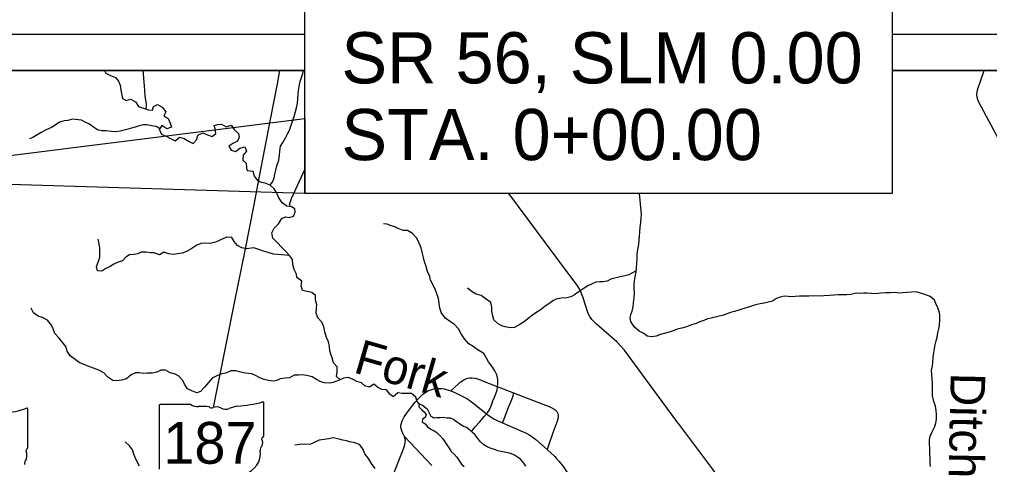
# Model space of a CAD drawing. Extents: x 0 to 36.5, y 0 to 25.3.
# Drawn here: x 3.798 to 6.451, y 19.822 to 21.04 of the extents above; entities that cross this region are included whole.
import ezdxf

# ---------------------------------------------------------------- set-up
doc = ezdxf.new("R2010")
doc.units = 0
for name, color, linetype in [('DV_X_Township_Line', 7, 'Continuous'), ('GM_X_County_Road', 7, 'Continuous'), ('GM_X_Major_Lake', 7, 'Continuous'), ('GM_X_Minor_River', 7, 'Continuous'), ('GM_X_Minor_River_Text', 7, 'Continuous'), ('GM_X_State_Route', 7, 'Continuous'), ('GM_X_State_Shield', 7, 'Continuous'), ('GM_X_Township_Road', 7, 'Continuous'), ('SH_Cut_Line', 7, 'Continuous'), ('SH_Data', 7, 'Continuous'), ('SH_Text', 7, 'Continuous'), ('SN_X_Public', 7, 'Continuous')]:
    doc.layers.add(name, color=color, linetype=linetype)

msp = doc.modelspace()

# ---------------------------------------------------------------- linework, layer by layer
at = {"layer": 'DV_X_Township_Line'}
for points in [[(4.5783, 20.9), (3.3366, 20.9), (3.2612, 20.6041), (2.8463, 19.037), (2.6265, 18.2595), (2.5271, 17.8912), (2.5226, 17.8751), (2.5165, 17.8524), (2.5144, 17.8445), (2.4192, 17.4891), (2.3437, 17.2326), (2.3403, 17.2198), (2.1039, 16.2931), (2.4938, 16.3413), (4.0938, 16.595), (4.8891, 16.7511), (5.1383, 16.6527), (6.6079, 15.9978)], [(6.9868, 20.9), (6.1845, 20.9)]]:
    msp.add_lwpolyline(points, dxfattribs=at)
at = {"layer": 'GM_X_County_Road'}
for points in [[(6.5695, 20.538), (6.4286, 20.8002), (6.4203, 20.8169), (6.4171, 20.8261), (6.416, 20.8349), (6.418, 20.8471), (6.4364, 20.9)], [(5.6026, 19.9308), (5.5959, 19.9396), (5.4521, 20.1349), (5.432, 20.1577), (5.3759, 20.2062), (5.3629, 20.2192), (5.3574, 20.2272), (5.3532, 20.2358), (5.339, 20.281), (5.331, 20.2995), (5.3245, 20.3101), (5.2656, 20.3899), (5.1365, 20.5634)], [(6.27, 19.0102), (6.154, 19.0787), (5.9106, 19.2156), (5.8953, 19.2261), (5.8889, 19.2321), (5.8831, 19.2395), (5.874, 19.2561), (5.8715, 19.2656), (5.8706, 19.2751), (5.8855, 19.4287), (5.8883, 19.4658), (5.8884, 19.4882), (5.8862, 19.5068), (5.882, 19.5251), (5.8767, 19.5387), (5.871, 19.5497), (5.8458, 19.5924), (5.8291, 19.6185), (5.7328, 19.7554), (5.6929, 19.8107), (5.6026, 19.9308)]]:
    msp.add_lwpolyline(points, dxfattribs=at)
at = {"layer": 'GM_X_Major_Lake'}
msp.add_lwpolyline([(5.1824, 19.8174), (5.1771, 19.8257), (5.1691, 19.836), (5.1596, 19.8425), (5.1517, 19.8478), (5.1437, 19.8516), (5.138, 19.8536), (5.1293, 19.8551), (5.1202, 19.857), (5.1145, 19.8578), (5.1061, 19.8601), (5.0966, 19.8632), (5.0883, 19.8662), (5.0769, 19.8708), (5.0678, 19.8762), (5.0587, 19.8845), (5.0515, 19.8933), (5.0443, 19.9032), (5.0368, 19.9101), (5.0288, 19.9169), (5.0205, 19.9234), (5.0106, 19.9268), (5.0011, 19.9337), (4.9932, 19.939), (4.9844, 19.9455), (4.9765, 19.9486), (4.967, 19.9494), (4.9567, 19.9505), (4.948, 19.9502), (4.9396, 19.9502), (4.9317, 19.9487), (4.9233, 19.9533), (4.9195, 19.9624), (4.915, 19.9715), (4.9078, 19.9773), (4.9002, 19.9834), (4.8907, 19.9883), (4.8903, 19.98), (4.8979, 19.9723), (4.9059, 19.9659), (4.91, 19.9583), (4.9077, 19.9507), (4.8997, 19.9465), (4.899, 19.9389), (4.9069, 19.934), (4.9137, 19.9256), (4.9228, 19.9191), (4.9316, 19.9145), (4.9395, 19.9099), (4.9471, 19.9012), (4.9554, 19.8924), (4.9615, 19.884), (4.9664, 19.8761), (4.9728, 19.8669), (4.9785, 19.8582), (4.9868, 19.8509), (4.994, 19.8425), (5.0012, 19.8315), (5.0065, 19.8235), (5.0137, 19.8167)], dxfattribs=at)
at = {"layer": 'GM_X_Minor_River'}
for points in [[(4.0305, 20.9), (4.0339, 20.893), (4.0467, 20.8865), (4.06, 20.8807), (4.0682, 20.8707), (4.0731, 20.8601), (4.0748, 20.8475), (4.0766, 20.8369), (4.0799, 20.8239), (4.0898, 20.8182), (4.1023, 20.8215), (4.1155, 20.8141), (4.1234, 20.8016), (4.1366, 20.7973), (4.1502, 20.7926), (4.162, 20.7921), (4.164, 20.8016), (4.1754, 20.8072), (4.1879, 20.7995), (4.1984, 20.7873), (4.193, 20.7759), (4.2047, 20.7686), (4.2099, 20.7557), (4.2132, 20.745), (4.201, 20.7409), (4.1874, 20.7494), (4.1801, 20.7384)], [(4.1442, 20.7947), (4.1454, 20.8086), (4.1433, 20.8189), (4.1411, 20.8306), (4.1405, 20.8454), (4.1394, 20.8584), (4.1388, 20.8679), (4.1377, 20.8781), (4.1371, 20.8918), (4.1359, 20.9)], [(4.4834, 20.5866), (4.491, 20.5961), (4.4941, 20.6067), (4.4964, 20.6169), (4.4991, 20.6272), (4.5017, 20.6397), (4.5067, 20.6549), (4.509, 20.6689), (4.5095, 20.6792), (4.5114, 20.6933), (4.5183, 20.7035), (4.5251, 20.7156), (4.5301, 20.7251), (4.5362, 20.7369), (4.5408, 20.7505), (4.5454, 20.7646), (4.5492, 20.7741), (4.5515, 20.7843), (4.555, 20.798), (4.5581, 20.8109), (4.5592, 20.8231), (4.5604, 20.836), (4.5608, 20.8455), (4.5624, 20.8561), (4.5658, 20.8698), (4.5693, 20.8815), (4.5727, 20.8922), (4.5745, 20.9)], [(4.1815, 20.7405), (4.1715, 20.7469), (4.159, 20.7493), (4.1457, 20.752), (4.1358, 20.7517), (4.1252, 20.7488), (4.1145, 20.7454), (4.1008, 20.7418), (4.0879, 20.7381), (4.0735, 20.734), (4.0613, 20.7326), (4.0484, 20.7335), (4.0351, 20.7351), (4.0226, 20.7356), (4.0113, 20.7383), (4.0003, 20.7453), (3.989, 20.7533), (3.9777, 20.7587), (3.9671, 20.7641), (3.9428, 20.7674), (3.9303, 20.7637), (3.9197, 20.7626), (3.9071, 20.7586), (3.8949, 20.7503), (3.885, 20.7447), (3.8709, 20.738), (3.8572, 20.7309), (3.8476, 20.7249), (3.8346, 20.7166), (3.8251, 20.7133)], [(4.1801, 20.7384), (4.1868, 20.7255), (4.1974, 20.7212), (4.2125, 20.7131), (4.2231, 20.7077), (4.2357, 20.7179), (4.2486, 20.714), (4.2614, 20.7063), (4.2731, 20.7009), (4.2827, 20.7114), (4.2851, 20.7235), (4.2988, 20.7295), (4.3116, 20.7241), (4.3245, 20.7194), (4.3348, 20.7281), (4.3327, 20.7402), (4.3305, 20.7501), (4.3404, 20.7527), (4.3502, 20.753), (4.3634, 20.7457), (4.3764, 20.7505), (4.3861, 20.7379), (4.3971, 20.7283), (4.3989, 20.718), (4.3942, 20.7067), (4.3813, 20.7003), (4.3702, 20.6932), (4.3769, 20.6825), (4.3886, 20.6783), (4.4005, 20.6873), (4.4138, 20.691), (4.4186, 20.6791), (4.4098, 20.6682), (4.4086, 20.6553), (4.4179, 20.6463), (4.4188, 20.6343), (4.4202, 20.6254)], [(4.8907, 19.9883), (4.8851, 19.9944), (4.8821, 20.0062), (4.8696, 20.0161), (4.8578, 20.0161), (4.8445, 20.0166), (4.8323, 20.0185), (4.8198, 20.0075), (4.8103, 20.0151), (4.8016, 20.0262), (4.7891, 20.0277), (4.7777, 20.0331), (4.7671, 20.0418), (4.7553, 20.0339), (4.7424, 20.0373), (4.7329, 20.0453), (4.7208, 20.0496), (4.709, 20.0553), (4.6965, 20.0606), (4.6839, 20.0584), (4.6744, 20.0539), (4.6646, 20.063), (4.6665, 20.0759), (4.6666, 20.0896), (4.6563, 20.1006), (4.653, 20.1139), (4.6496, 20.1238), (4.6465, 20.1333), (4.6458, 20.1455), (4.6428, 20.158), (4.6372, 20.1702), (4.6326, 20.1854), (4.6304, 20.1991), (4.6251, 20.212), (4.6134, 20.2234), (4.6089, 20.2364), (4.6104, 20.2497), (4.6108, 20.2595), (4.6078, 20.2717), (4.6071, 20.285), (4.5972, 20.2926), (4.5847, 20.2957), (4.5722, 20.2984), (4.568, 20.3109), (4.5696, 20.3242), (4.5567, 20.3338), (4.5552, 20.3433), (4.5488, 20.3558), (4.5454, 20.3691), (4.5447, 20.3828), (4.536, 20.3938), (4.5269, 20.4041), (4.5152, 20.4163), (4.5023, 20.4296), (4.4909, 20.4414), (4.4876, 20.4563), (4.4944, 20.4692), (4.5066, 20.4809), (4.515, 20.4957), (4.5249, 20.5002), (4.5352, 20.4979), (4.5473, 20.5017), (4.5519, 20.5123), (4.5508, 20.5218), (4.5413, 20.5268), (4.5288, 20.5295), (4.5163, 20.5386), (4.5068, 20.5516), (4.5015, 20.5645), (4.4947, 20.5763), (4.4834, 20.5866), (4.4701, 20.5916), (4.4598, 20.5939), (4.4504, 20.5984), (4.4409, 20.611), (4.4368, 20.6239), (4.4202, 20.6254)], [(4.5378, 20.5275), (4.5372, 20.5367), (4.5414, 20.5503), (4.5783, 20.6297)], [(6.2742, 20.2878), (6.2594, 20.292), (6.2499, 20.2943), (6.2377, 20.2936), (6.2252, 20.2925), (6.2142, 20.2921), (6.2024, 20.291), (6.1929, 20.2926), (6.1789, 20.2915), (6.1663, 20.2915), (6.153, 20.2908), (6.1397, 20.2893), (6.1283, 20.2905), (6.1162, 20.2912), (6.1067, 20.2909), (6.0964, 20.2905), (6.0869, 20.2909), (6.0714, 20.2872), (6.0611, 20.2868), (6.0474, 20.2865), (6.0372, 20.2869), (6.0258, 20.2854), (6.0136, 20.2847), (5.9977, 20.2836), (5.9847, 20.2829), (5.9726, 20.2833), (5.9563, 20.2826), (5.9308, 20.2826), (5.9198, 20.2819), (5.9099, 20.2812), (5.9, 20.2823), (5.889, 20.2824), (5.878, 20.2805), (5.8681, 20.2767), (5.8571, 20.2692), (5.8453, 20.2661), (5.8343, 20.2639), (5.8233, 20.262), (5.8107, 20.259), (5.8001, 20.2556), (5.789, 20.2522), (5.7765, 20.2485), (5.7651, 20.2447), (5.7533, 20.2413), (5.7427, 20.2379), (5.7237, 20.2311), (5.7039, 20.2263), (5.6894, 20.2229), (5.6799, 20.2206), (5.6693, 20.2161), (5.6583, 20.2123), (5.6484, 20.2082), (5.6358, 20.204), (5.6225, 20.1987), (5.6096, 20.1954), (5.5963, 20.1923), (5.5853, 20.1882), (5.5746, 20.1844), (5.5613, 20.1807), (5.5511, 20.1777), (5.5389, 20.1731), (5.526, 20.1716), (5.5146, 20.1736), (5.5051, 20.1804), (5.4926, 20.1873), (5.4793, 20.1991), (5.4702, 20.2132), (5.4684, 20.2227), (5.4703, 20.2326), (5.4738, 20.2421), (5.4761, 20.2538), (5.4772, 20.2648), (5.4792, 20.2789), (5.48, 20.2922), (5.4792, 20.3036), (5.4793, 20.3142), (5.4801, 20.3249), (5.4816, 20.3359), (5.4847, 20.3495), (5.4851, 20.3594), (5.4863, 20.3723), (5.4871, 20.3849), (5.4875, 20.3985), (5.489, 20.4103), (5.4921, 20.4251), (5.4925, 20.4369), (5.4933, 20.4468), (5.4945, 20.4582), (5.4957, 20.4715), (5.4972, 20.484), (5.4984, 20.4961), (5.4988, 20.5072), (5.494, 20.5634)], [(5.0338, 19.9126), (5.0444, 19.9256), (5.0566, 19.9393), (5.0684, 19.9533), (5.0772, 19.9628), (5.0833, 19.9722), (5.0879, 19.9832), (5.0928, 19.9961), (5.0971, 20.0064), (5.1032, 20.0227), (5.1051, 20.0322), (5.1059, 20.0451), (5.1063, 20.0546), (5.1033, 20.0672), (5.0976, 20.0786), (5.0893, 20.0911), (5.081, 20.1029), (5.0753, 20.1132), (5.0674, 20.1258), (5.0496, 20.1368), (5.0389, 20.1448), (5.0268, 20.1528), (5.0151, 20.1665), (5.006, 20.1799), (4.9988, 20.1932), (4.9875, 20.2054), (4.9738, 20.2141), (4.9643, 20.2214), (4.9522, 20.2362), (4.9473, 20.2499), (4.9458, 20.2621), (4.9444, 20.2723), (4.9421, 20.2822), (4.9387, 20.2917), (4.9346, 20.3016), (4.9221, 20.3267), (4.9198, 20.3366), (4.9134, 20.3503), (4.9097, 20.3636), (4.9059, 20.3765), (4.9029, 20.3883), (4.8988, 20.4031), (4.8961, 20.4153), (4.8912, 20.4275), (4.8844, 20.4412), (4.8727, 20.4541), (4.8594, 20.4621), (4.8469, 20.4629), (4.8336, 20.4679), (4.8241, 20.4729), (4.8139, 20.4755), (4.8036, 20.4794), (4.7938, 20.4809)], [(4.4184, 20.4127), (4.4061, 20.4151), (4.394, 20.4216), (4.3853, 20.4327), (4.3786, 20.4434), (4.3653, 20.4442), (4.3539, 20.4394), (4.3406, 20.4334), (4.3307, 20.4297), (4.3181, 20.4268), (4.3041, 20.428), (4.2938, 20.4266), (4.2832, 20.4221), (4.2691, 20.4135), (4.255, 20.4053), (4.2428, 20.4005), (4.2302, 20.3983), (4.22, 20.3969), (4.206, 20.3985), (4.1927, 20.4035), (4.1805, 20.3957), (4.1661, 20.4011), (4.1563, 20.4012), (4.1438, 20.4032), (4.1309, 20.4033), (4.1213, 20.3984), (4.1107, 20.3966), (4.0986, 20.396), (4.0886, 20.3896), (4.0794, 20.3794), (4.0695, 20.3769), (4.0554, 20.3701), (4.0455, 20.3638), (4.0341, 20.3589), (4.0234, 20.3514), (4.0109, 20.3523), (4.0083, 20.3637), (4.013, 20.3762), (4.0177, 20.3891), (4.0174, 20.4016), (4.0179, 20.4141), (4.0161, 20.4263), (4.0132, 20.4388)], [(4.536, 20.3938), (4.5151, 20.3958), (4.5037, 20.3966), (4.4927, 20.3978), (4.4775, 20.402), (4.4654, 20.4062), (4.4525, 20.4104), (4.4388, 20.4154), (4.4184, 20.4127)], [(5.4848, 20.3526), (5.474, 20.3465), (5.4645, 20.3412), (5.4501, 20.3375), (5.4406, 20.3356), (5.4261, 20.3322), (5.4151, 20.3292), (5.4049, 20.3243), (5.3946, 20.3217), (5.3851, 20.3225), (5.3741, 20.321), (5.3627, 20.3161), (5.352, 20.3111), (5.3398, 20.3032), (5.3261, 20.2934), (5.3159, 20.2862), (5.306, 20.2809), (5.2946, 20.2782), (5.2794, 20.2775), (5.2661, 20.2749), (5.2562, 20.27), (5.2459, 20.262), (5.236, 20.2552), (5.2219, 20.2443), (5.2124, 20.239), (5.201, 20.2306), (5.1884, 20.2204), (5.1782, 20.2128), (5.1648, 20.2045), (5.1519, 20.1973), (5.1397, 20.1962), (5.1265, 20.1985), (5.1166, 20.202), (5.1067, 20.2073), (5.095, 20.2184), (5.0912, 20.2321), (5.0901, 20.2419), (5.0894, 20.2526), (5.0871, 20.2651), (5.0743, 20.2743), (5.0606, 20.2846), (5.047, 20.2884), (5.036, 20.2945), (5.0234, 20.3048)], [(6.2892, 19.8167), (6.2888, 19.8265), (6.2889, 19.8394), (6.2881, 19.8535), (6.2878, 19.8687), (6.2867, 19.8782), (6.2867, 19.8896), (6.289, 19.9002), (6.2952, 19.9139), (6.3005, 19.9245), (6.3043, 19.9355), (6.3059, 19.9465), (6.3059, 19.9587), (6.3052, 19.9701), (6.3029, 19.9823), (6.2984, 19.9948), (6.2954, 20.01), (6.2951, 20.0222), (6.2951, 20.0317), (6.2948, 20.0442), (6.2944, 20.0556), (6.2929, 20.0697), (6.2918, 20.0792), (6.2953, 20.0921), (6.2957, 20.1016), (6.2972, 20.116), (6.2988, 20.1285), (6.3003, 20.1392), (6.3019, 20.1494), (6.305, 20.1608), (6.3077, 20.1703), (6.31, 20.1821), (6.3123, 20.1935), (6.3138, 20.2033), (6.3154, 20.2189), (6.315, 20.2314), (6.3132, 20.2409), (6.3098, 20.2505), (6.3045, 20.2626), (6.3003, 20.2721), (6.2882, 20.2817), (6.2742, 20.2878)], [(4.4146, 20.0718), (4.4034, 20.0746), (4.3898, 20.0781), (4.3754, 20.0786), (4.3624, 20.0726), (4.3499, 20.0705), (4.3377, 20.0652), (4.3248, 20.0589), (4.3037, 20.034), (4.2929, 20.0216), (4.283, 20.0186), (4.269, 20.0237), (4.257, 20.0295), (4.2491, 20.0424), (4.2443, 20.052), (4.2337, 20.0638), (4.2235, 20.0692), (4.2095, 20.0735), (4.1971, 20.0805), (4.1846, 20.0802), (4.1735, 20.0753), (4.1602, 20.0724), (4.1469, 20.0721), (4.137, 20.0711), (4.1249, 20.0731), (4.1154, 20.0728), (4.1036, 20.0676), (4.0906, 20.0571), (4.0769, 20.053), (4.0636, 20.0512), (4.0526, 20.0524), (4.0394, 20.0613), (4.0285, 20.0728), (4.0146, 20.0805), (4.0006, 20.0859), (3.9854, 20.091), (3.9733, 20.0956), (3.9613, 20.1014), (3.9496, 20.1095), (3.936, 20.1198), (3.9285, 20.1328), (3.9245, 20.1454), (3.9132, 20.1584), (3.9061, 20.1679), (3.8944, 20.1805), (3.8896, 20.1931), (3.8851, 20.2038), (3.8742, 20.2168), (3.861, 20.2241), (3.8486, 20.2284), (3.8357, 20.2368), (3.8294, 20.2502)], [(4.6744, 20.0539), (4.6558, 20.0463), (4.6463, 20.0444), (4.6319, 20.046), (4.622, 20.0487), (4.6102, 20.0544), (4.5985, 20.0624), (4.5833, 20.0655), (4.57, 20.0674), (4.5605, 20.0667), (4.5487, 20.0671), (4.5362, 20.0592), (4.524, 20.0581), (4.5111, 20.0566), (4.5012, 20.0517), (4.4913, 20.0505), (4.4792, 20.0525), (4.4674, 20.0548), (4.4553, 20.0594), (4.4431, 20.0659), (4.4333, 20.0701), (4.4146, 20.0718)], [(4.1257, 19.818), (4.119, 19.8317), (4.1141, 19.8412), (4.1108, 19.8508), (4.1067, 19.8626), (4.0985, 19.8736), (4.0864, 19.884)], [(4.7706, 19.8112), (4.7608, 19.8253), (4.7521, 19.8386), (4.7426, 19.8516), (4.7369, 19.8649), (4.7275, 19.8767), (4.7146, 19.8813), (4.7017, 19.8844), (4.6918, 19.887), (4.6823, 19.8886), (4.6687, 19.8928), (4.6561, 19.8955), (4.644, 19.8929), (4.631, 19.891), (4.617, 19.8891), (4.6041, 19.8827), (4.5919, 19.8774), (4.5786, 19.8775), (4.5645, 19.8771), (4.5512, 19.8753)]]:
    msp.add_lwpolyline(points, dxfattribs=at)
at = {"layer": 'GM_X_State_Route'}
for points in [[(4.4535, 20.6058), (4.4842, 20.7661), (4.5033, 20.8636), (4.5102, 20.9)], [(4.3282, 19.9783), (4.3628, 20.1506), (4.3704, 20.187), (4.3848, 20.2602), (4.4156, 20.4124), (4.4386, 20.5282), (4.4535, 20.6058)]]:
    msp.add_lwpolyline(points, dxfattribs=at)
at = {"layer": 'GM_X_State_Shield'}
for p, q in [((3.8205, 19.8682), (3.8205, 19.9729)), ((3.8204, 19.8682), (3.8205, 19.8682))]:
    msp.add_line(p, q, dxfattribs=at)
for centre, radius, start, end in [((3.7265, 20.2408), 0.2796, 275.8445, 288.9065), ((3.8175, 19.9733), 0.00294, 351.8621, 97.738), ((3.8198, 19.8605), 0.00454, 107.944, 210.337), ((3.7909, 19.8473), 0.0273, 340.033, 23.6496), ((3.8173, 19.8678), 0.00314, 289.6038, 7.7341), ((3.831, 19.8244), 0.0198, 136.8065, 186.9296)]:
    msp.add_arc(centre, radius, start, end, dxfattribs=at)
at = {"layer": 'GM_X_Township_Road'}
msp.add_line((4.9257, 19.8194), (4.8508, 19.8992), dxfattribs=at)
for points in [[(4.9773, 20.0237), (4.999, 20.044), (5.0035, 20.0477), (5.0132, 20.0543), (5.0184, 20.0568), (5.0239, 20.0587), (5.0295, 20.0597), (5.0357, 20.0598), (5.0438, 20.0587), (5.0532, 20.0561), (5.059, 20.0538), (5.0643, 20.051), (5.1492, 20.018)], [(4.8508, 19.8992), (4.8442, 19.9117), (4.8422, 19.9175), (4.841, 19.9236), (4.8411, 19.9298), (4.8423, 19.9353), (4.8445, 19.9417), (4.8471, 19.9473), (4.8501, 19.9528), (4.8642, 19.9732), (4.8796, 19.9925), (4.8879, 20.0017), (4.8966, 20.0105), (4.9012, 20.0146), (4.9061, 20.0184), (4.9121, 20.0222), (4.9168, 20.0247), (4.9225, 20.027), (4.9284, 20.0288), (4.9344, 20.03), (4.9406, 20.0306), (4.9468, 20.0306), (4.953, 20.03), (4.9591, 20.029), (4.9651, 20.0275), (4.9773, 20.0237)], [(4.9773, 20.0237), (4.9884, 20.0193), (5.0106, 20.0086), (5.0214, 20.0027), (5.0266, 19.9995), (5.0415, 19.9884), (5.0704, 19.9647), (5.08, 19.9577), (5.0955, 19.9475), (5.1064, 19.9418), (5.1185, 19.9361)], [(5.1185, 19.9361), (5.1231, 19.9469), (5.1364, 19.9812), (5.1442, 19.9998), (5.1476, 20.0098), (5.1492, 20.0158), (5.1492, 20.018)], [(5.1492, 20.018), (5.2295, 19.9876), (5.2467, 19.9807), (5.2523, 19.9781), (5.26, 19.9733), (5.2627, 19.9715), (5.2672, 19.9673), (5.2702, 19.9618), (5.2713, 19.9559), (5.2709, 19.9497), (5.2673, 19.9379), (5.2568, 19.909), (5.2451, 19.874), (5.241, 19.8633)], [(5.1185, 19.9361), (5.1686, 19.9148), (5.1799, 19.9097), (5.1909, 19.904), (5.1962, 19.9008), (5.2099, 19.8903), (5.241, 19.8633)], [(4.8151, 19.7817), (4.8387, 19.8419), (4.8436, 19.8533), (4.8477, 19.865), (4.85, 19.8707), (4.8519, 19.8766), (4.853, 19.8827), (4.8531, 19.8889), (4.8521, 19.895), (4.8508, 19.8992)], [(5.241, 19.8633), (5.2616, 19.8441), (5.266, 19.8397), (5.2742, 19.8304), (5.2854, 19.8158), (5.2939, 19.803), (5.3039, 19.7868)]]:
    msp.add_lwpolyline(points, dxfattribs=at)
at = {"layer": 'SH_Cut_Line'}
msp.add_lwpolyline([(4.4591, 20.9), (3.3366, 20.9), (3.2612, 20.6041), (2.8463, 19.037), (2.6265, 18.2595), (2.5271, 17.8912), (2.5226, 17.8751), (2.5165, 17.8524), (2.5144, 17.8445), (2.4192, 17.4891), (2.3437, 17.2326), (2.3403, 17.2198), (2.1039, 16.2931), (2.1, 16.2788), (2.1, 14.1), (8.9, 14.1), (8.9, 20.9), (6.1845, 20.9)], dxfattribs=at)
at = {"layer": 'SH_Data'}
for p, q in [((2, 21), (4.5783, 21)), ((6.1845, 21), (9, 21)), ((2.1, 20.9), (4.5783, 20.9)), ((6.1845, 20.9), (8.9, 20.9))]:
    msp.add_line(p, q, dxfattribs=at)
at = {"layer": 'SH_Text'}
for points in [[(4.5783, 21.315), (6.1845, 21.315), (6.1845, 20.5634), (4.5783, 20.5634)], [(3.2615, 20.6035), (4.5783, 20.7692), (4.5783, 20.5634)]]:
    msp.add_lwpolyline(points, close=True, dxfattribs=at)
at = {"layer": 'SN_X_Public'}
for p, q in [((4.1801, 19.9833), (4.1801, 19.8098)), ((4.2665, 19.9863), (4.1829, 19.9863)), ((4.4657, 19.8998), (4.4657, 19.9906)), ((4.4657, 19.8999), (4.4657, 19.8998))]:
    msp.add_line(p, q, dxfattribs=at)
for centre, major_axis, start_param, end_param in [((4.1833, 19.9837), (0.00331, 0), 1.712693, 3.28349), ((4.2865, 20.0064), (0.0321, 0), 4.042523, 4.731795), ((4.364, 20.2228), (0.303, 0), 4.814394, 5.042369), ((4.4626, 19.991), (0.00318, 0), 6.141152, 7.989035), ((4.2971, 19.8889), (0.1152, 0), 1.404758, 1.657858), ((4.3233, 19.9846), (0.00926, 0), 3.836095, 5.185415), ((4.3369, 19.9645), (0.0193, 0), 0.950623, 2.079405), ((4.3617, 19.992), (0.0232, 0), 4.081561, 5.145723), ((4.4026, 19.9333), (0.061, 0), 1.699011, 2.107814), ((4.465, 19.8932), (0.00492, 0), 1.883978, 3.671073), ((4.4337, 19.8817), (0.0295, 0), 5.934695, 6.695948), ((4.4623, 19.8995), (0.0034, 0), 5.05454, 6.418171), ((4.3809, 19.8503), (0.0758, 0), 5.101752, 6.440018), ((4.4771, 19.8619), (0.0215, 0), 2.387724, 3.262537)]:
    msp.add_ellipse(centre, major_axis=major_axis, ratio=0.8, start_param=start_param, end_param=end_param, dxfattribs=at)

# ---------------------------------------------------------------- texts
at = {"layer": 'GM_X_Minor_River_Text'}
for s, rotation, p in [('Fork', 343.8325, (4.7081, 20.0749)), ('Ditch', 268.8281, (6.3449, 20.0739))]:
    msp.add_text(s, height=0.09469, rotation=rotation, dxfattribs=at).set_placement(p)
at = {"layer": 'SH_Text'}
for s, p in [('SR 56, SLM 0.00', (4.6783, 20.865)), ('STA. 0+00.00', (4.6783, 20.655))]:
    msp.add_text(s, height=0.14, dxfattribs=at).set_placement(p)
at = {"layer": 'SN_X_Public'}
msp.add_text('187', height=0.11427, dxfattribs=at).set_placement((4.1911, 19.8244))

doc.saveas('drawing.dxf')
